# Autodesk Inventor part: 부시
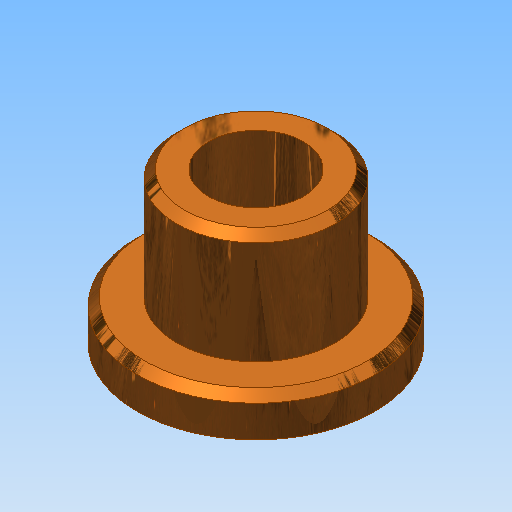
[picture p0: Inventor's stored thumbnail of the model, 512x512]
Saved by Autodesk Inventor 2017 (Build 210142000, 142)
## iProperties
Created: 2016-02
Part Number: 부시
Material: 스테인리스강
Document SubType Name: Modeling
Designer: mduedu
Density: 8.08 g/cm^3
Appearance: 금속 1600F 열
Author: mduedu
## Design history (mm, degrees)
sketch "스케치1"
  geometry: C1 r 15 at (0, 0); 1 further point
  constraints: 1 centre point, 1 coincident
  dimensions: "d0" = 30 diameter of C1
extrude "돌출1" new body sketch "스케치1" distance "d1" = 5; taper "d2" = 0 deg
sketch "스케치2"
  geometry: C1 r 10 at (0, 0); 1 further point
  constraints: 1 centre point, 1 coincident
  dimensions: "d3" = 20 diameter of C1
extrude "돌출2" join sketch "스케치2" distance "d4" = 14; taper "d5" = 0 deg
hole "구멍1" diameter "d8" = 12; stored, may be unused: countersink angle "d12" = 90 deg, drill point angle "d14" = 118 deg; dims "d9" = 6, "d10" = 4, "d11" = 2, "d13" = 8, "d15" = 10, "d16" = 10
chamfer "모따기1" distance "d17" = 1; stored, may be unused: second distance "d18" = 2, angle "d19" = 45 deg
chamfer "모따기2" distance "d20" = 1; stored, may be unused: second distance "d21" = 2, angle "d22" = 45 deg
chamfer "모따기3" distance "d23" = 1; stored, may be unused: second distance "d24" = 2, angle "d25" = 45 deg
node "솔리드1"
